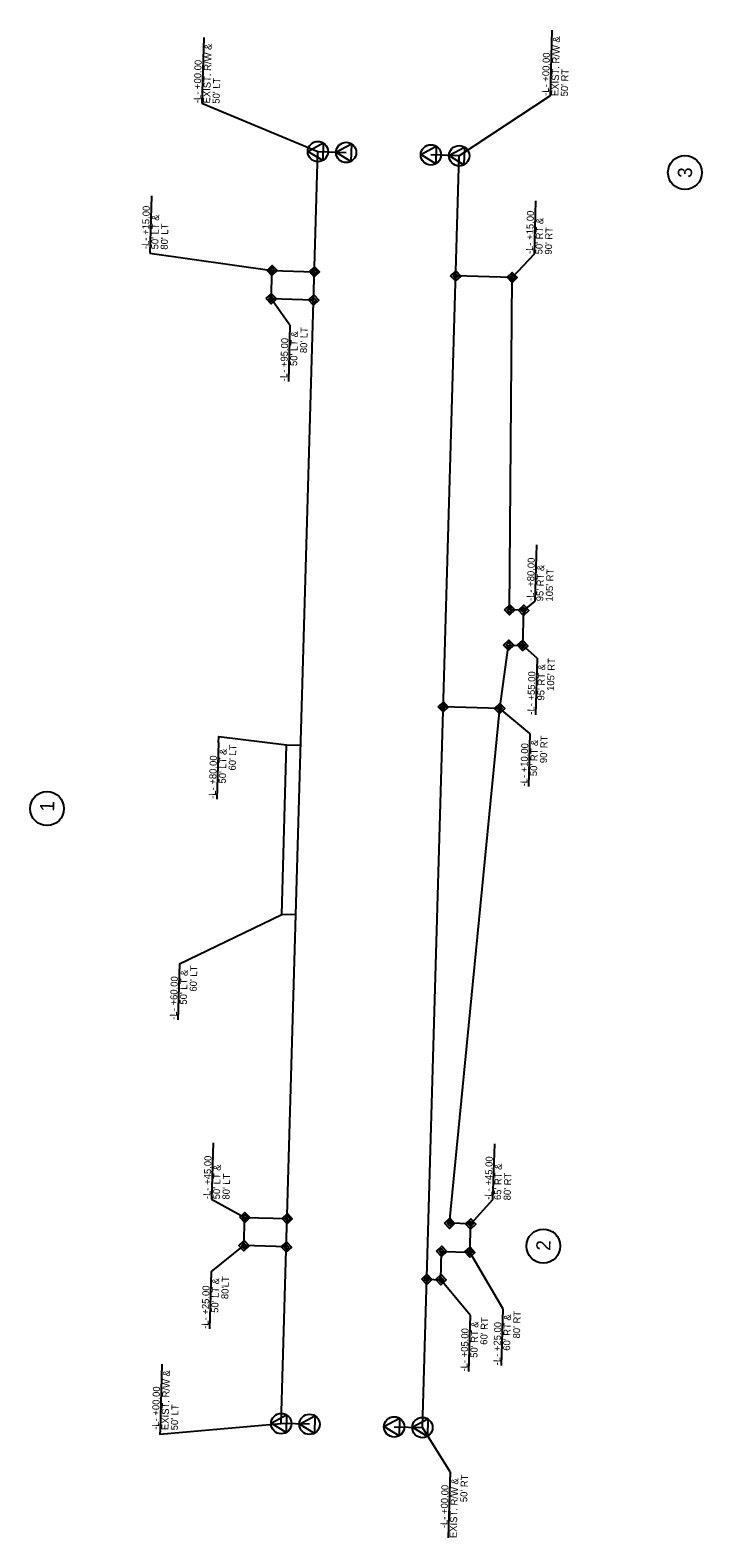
# Model space of a CAD drawing. Extents: x 2097753 to 2098985, y 990579 to 991646.
# Drawn here: x 2098509 to 2098985, y 990579 to 991646 of the extents above; entities that cross this region are included whole.
import ezdxf

# ---------------------------------------------------------------- set-up
doc = ezdxf.new("R2010")
doc.units = 0
for name, color, linetype in [('Prop DSN Text', 7, 'Continuous'), ('Prop Easement Construction', 7, 'Continuous'), ('Prop Easement Construction Station Offsets', 7, 'Continuous'), ('Prop Easement Permanent Drainage Utility', 7, 'Continuous'), ('Prop Easement Permanent Drainage Utility Station Offsets', 7, 'Continuous'), ('Prop Easement Permanent Utility', 7, 'Continuous'), ('Prop Easement Permanent Utility Station Offsets', 7, 'Continuous'), ('Prop Parcel Number CELL', 7, 'Continuous'), ('Prop ROW Marker CELL', 7, 'Continuous'), ('Prop ROW Permanent Easement CELL', 7, 'Continuous'), ('Prop ROW RW Lines', 7, 'Continuous'), ('Prop ROW Station Offsets', 7, 'Continuous')]:
    doc.layers.add(name, color=color, linetype=linetype)

msp = doc.modelspace()

# ---------------------------------------------------------------- linework, layer by layer
at = {"layer": 'Prop Easement Construction'}
msp.add_lwpolyline([(2098697.4, 991019.8), (2098687.5, 991020.1), (2098690.9, 991140), (2098700.9, 991139.7)], dxfattribs=at)
at = {"layer": 'Prop Easement Construction Station Offsets'}
for p, q in [((2098642.7, 991141.6), (2098641.6, 991101.7)), ((2098615.1, 990985.2), (2098614, 990945.5))]:
    msp.add_line(p, q, dxfattribs=at)
for points in [[(2098642.7, 991141.6), (2098642.9, 991145.8), (2098690.9, 991140)], [(2098615.1, 990985.2), (2098687.5, 991020.1)]]:
    msp.add_lwpolyline(points, dxfattribs=at)
at = {"layer": 'Prop Easement Permanent Drainage Utility'}
for p, q in [((2098850.5, 991470.6), (2098810.5, 991471.7)), ((2098848.7, 991235.5), (2098850.5, 991470.6)), ((2098858.7, 991235.2), (2098848.7, 991235.5)), ((2098858, 991210.3), (2098858.7, 991235.2)), ((2098841.7, 991165.7), (2098848, 991210.5)), ((2098848, 991210.5), (2098858, 991210.3))]:
    msp.add_line(p, q, dxfattribs=at)
at = {"layer": 'Prop Easement Permanent Drainage Utility Station Offsets'}
for p, q in [((2098867.1, 991524.8), (2098866, 991487)), ((2098867.7, 991281.5), (2098866.6, 991241.7)), ((2098868.2, 991201.4), (2098867, 991161.3))]:
    msp.add_line(p, q, dxfattribs=at)
for points in [[(2098866, 991487), (2098850.5, 991470.6)], [(2098866.6, 991241.7), (2098858.7, 991235.2)], [(2098868.2, 991201.4), (2098858, 991210.3)]]:
    msp.add_lwpolyline(points, dxfattribs=at)
at = {"layer": 'Prop Easement Permanent Utility'}
for points in [[(2098710, 991454.6), (2098680, 991455.5), (2098680.6, 991475.5), (2098710.6, 991474.6)], [(2098790.1, 990762), (2098800.1, 990761.7), (2098800.6, 990781.7), (2098820.6, 990781.1), (2098821.2, 990801.1), (2098806.2, 990801.6), (2098841.7, 991165.7), (2098801.7, 991166.9)], [(2098690.7, 990784.9), (2098660.7, 990785.8), (2098661.3, 990805.7), (2098691.3, 990804.9)]]:
    msp.add_lwpolyline(points, dxfattribs=at)
at = {"layer": 'Prop Easement Permanent Utility Station Offsets'}
for p, q in [((2098595.2, 991528.3), (2098594, 991487.8)), ((2098693.2, 991436.9), (2098692.1, 991397.1)), ((2098863.1, 991148.1), (2098862, 991110.5)), ((2098638.9, 990858.5), (2098637.7, 990818.7)), ((2098837.9, 990857.9), (2098836.7, 990818.1)), ((2098637.5, 990767.2), (2098636.3, 990726.9)), ((2098844, 990741.3), (2098842.8, 990701)), ((2098820.8, 990736.6), (2098819.7, 990696.7))]:
    msp.add_line(p, q, dxfattribs=at)
for points in [[(2098594, 991487.8), (2098680.6, 991475.5)], [(2098693.2, 991436.9), (2098680, 991455.5)], [(2098863.1, 991148.1), (2098841.7, 991165.7)], [(2098637.7, 990818.7), (2098661.3, 990805.7)], [(2098836.7, 990818.1), (2098821.2, 990801.1)], [(2098637.5, 990767.2), (2098660.7, 990785.8)], [(2098844, 990741.3), (2098820.6, 990781.1)], [(2098820.8, 990736.6), (2098800.1, 990761.7)]]:
    msp.add_lwpolyline(points, dxfattribs=at)
at = {"layer": 'Prop Parcel Number CELL'}
for p, q in [((2098972.8, 991544.8), (2098972.8, 991544.8)), ((2098521.3, 991094.9), (2098521.3, 991094.9)), ((2098872.6, 990785.5), (2098872.6, 990785.5))]:
    msp.add_line(p, q, dxfattribs=at)
for centre in [(2098972.8, 991544.8), (2098521.3, 991094.9), (2098872.6, 990785.5)]:
    msp.add_circle(centre, 12, dxfattribs=at)
at = {"layer": 'Prop ROW Marker CELL'}
for p, q in [((2098713, 991559.6), (2098713, 991559.6)), ((2098733, 991559), (2098733, 991559)), ((2098793, 991557.3), (2098793, 991557.3)), ((2098813, 991556.7), (2098813, 991556.7)), ((2098680.6, 991475.5), (2098680.6, 991475.5)), ((2098710.6, 991474.6), (2098710.6, 991474.6)), ((2098810.5, 991471.7), (2098810.5, 991471.7)), ((2098850.5, 991470.6), (2098850.5, 991470.6)), ((2098680, 991455.5), (2098680, 991455.5)), ((2098710, 991454.6), (2098710, 991454.6)), ((2098848.7, 991235.5), (2098848.7, 991235.5)), ((2098858.7, 991235.2), (2098858.7, 991235.2)), ((2098848, 991210.5), (2098848, 991210.5)), ((2098858, 991210.3), (2098858, 991210.3)), ((2098801.7, 991166.9), (2098801.7, 991166.9)), ((2098841.7, 991165.7), (2098841.7, 991165.7)), ((2098661.3, 990805.7), (2098661.3, 990805.7)), ((2098691.3, 990804.9), (2098691.3, 990804.9)), ((2098806.2, 990801.6), (2098806.2, 990801.6)), ((2098821.2, 990801.1), (2098821.2, 990801.1)), ((2098660.7, 990785.8), (2098660.7, 990785.8)), ((2098690.7, 990784.9), (2098690.7, 990784.9)), ((2098800.6, 990781.7), (2098800.6, 990781.7)), ((2098820.6, 990781.1), (2098820.6, 990781.1)), ((2098790.1, 990762), (2098790.1, 990762)), ((2098800.1, 990761.7), (2098800.1, 990761.7)), ((2098687.1, 990659.9), (2098687.1, 990659.9)), ((2098707.1, 990659.4), (2098707.1, 990659.4)), ((2098767, 990657.6), (2098767, 990657.6)), ((2098787, 990657.1), (2098787, 990657.1))]:
    msp.add_line(p, q, dxfattribs=at)
for points in [[(2098716.4, 991553.2), (2098705.8, 991559.8), (2098716.8, 991565.7)], [(2098736.4, 991552.6), (2098725.8, 991559.2), (2098736.8, 991565.1)], [(2098796.4, 991550.9), (2098785.8, 991557.5), (2098796.7, 991563.4)], [(2098816.4, 991550.3), (2098805.8, 991556.9), (2098816.7, 991562.8)], [(2098690.5, 990653.6), (2098679.9, 990660.2), (2098690.9, 990666.1)], [(2098710.5, 990653), (2098699.9, 990659.6), (2098710.8, 990665.5)], [(2098770.5, 990651.3), (2098759.8, 990657.8), (2098770.8, 990663.8)], [(2098790.5, 990650.7), (2098779.8, 990657.3), (2098790.8, 990663.2)]]:
    msp.add_lwpolyline(points, close=True, dxfattribs=at)
for centre in [(2098713, 991559.6), (2098733, 991559), (2098793, 991557.3), (2098813, 991556.7), (2098687.1, 990659.9), (2098707.1, 990659.4), (2098767, 990657.6), (2098787, 990657.1)]:
    msp.add_circle(centre, 7.2, dxfattribs=at)
at = {"layer": 'Prop ROW Permanent Easement CELL'}
for points in [[(2098677, 991475.6), (2098680.7, 991479.1), (2098684.2, 991475.4), (2098680.5, 991471.9)], [(2098678.8, 991475.5), (2098680.6, 991477.3), (2098682.4, 991475.4), (2098680.5, 991473.7)], [(2098707, 991474.7), (2098710.7, 991478.2), (2098714.1, 991474.5), (2098710.4, 991471)], [(2098708.8, 991474.7), (2098710.6, 991476.4), (2098712.4, 991474.6), (2098710.5, 991472.8)], [(2098806.9, 991471.8), (2098810.6, 991475.3), (2098814.1, 991471.6), (2098810.4, 991468.1)], [(2098808.7, 991471.8), (2098810.6, 991473.5), (2098812.3, 991471.7), (2098810.5, 991469.9)], [(2098846.9, 991470.7), (2098850.6, 991474.2), (2098854.1, 991470.5), (2098850.4, 991467)], [(2098848.7, 991470.6), (2098850.5, 991472.4), (2098852.3, 991470.5), (2098850.4, 991468.8)], [(2098676.4, 991455.6), (2098680.1, 991459.1), (2098683.6, 991455.4), (2098679.9, 991451.9)], [(2098678.2, 991455.5), (2098680, 991457.3), (2098681.8, 991455.4), (2098679.9, 991453.7)], [(2098706.4, 991454.7), (2098710.1, 991458.2), (2098713.6, 991454.5), (2098709.9, 991451)], [(2098708.2, 991454.7), (2098710, 991456.4), (2098711.8, 991454.6), (2098709.9, 991452.8)], [(2098845.1, 991235.6), (2098848.8, 991239.1), (2098852.3, 991235.4), (2098848.6, 991231.9)], [(2098846.9, 991235.6), (2098848.8, 991237.3), (2098850.5, 991235.5), (2098848.7, 991233.7)], [(2098855.1, 991235.3), (2098858.8, 991238.8), (2098862.3, 991235.1), (2098858.6, 991231.6)], [(2098856.9, 991235.3), (2098858.8, 991237), (2098860.5, 991235.2), (2098858.7, 991233.4)], [(2098844.4, 991210.6), (2098848.1, 991214.1), (2098851.6, 991210.4), (2098847.9, 991206.9)], [(2098846.2, 991210.6), (2098848.1, 991212.3), (2098849.8, 991210.5), (2098848, 991208.7)], [(2098854.4, 991210.4), (2098858.1, 991213.8), (2098861.6, 991210.1), (2098857.9, 991206.7)], [(2098856.2, 991210.3), (2098858.1, 991212), (2098859.8, 991210.2), (2098857.9, 991208.5)], [(2098798.1, 991167), (2098801.8, 991170.5), (2098805.3, 991166.7), (2098801.6, 991163.3)], [(2098799.9, 991166.9), (2098801.8, 991168.7), (2098803.5, 991166.8), (2098801.7, 991165.1)], [(2098838.1, 991165.8), (2098841.8, 991169.3), (2098845.3, 991165.6), (2098841.6, 991162.1)], [(2098839.9, 991165.8), (2098841.8, 991167.5), (2098843.5, 991165.6), (2098841.7, 991163.9)], [(2098657.7, 990805.9), (2098661.4, 990809.3), (2098664.9, 990805.6), (2098661.2, 990802.2)], [(2098659.5, 990805.8), (2098661.3, 990807.5), (2098663.1, 990805.7), (2098661.2, 990803.9)], [(2098687.7, 990805), (2098691.4, 990808.5), (2098694.9, 990804.8), (2098691.2, 990801.3)], [(2098689.5, 990804.9), (2098691.3, 990806.7), (2098693.1, 990804.8), (2098691.2, 990803.1)], [(2098802.6, 990801.7), (2098806.3, 990805.2), (2098809.8, 990801.5), (2098806.1, 990798)], [(2098817.6, 990801.2), (2098821.3, 990804.7), (2098824.8, 990801), (2098821.1, 990797.5)], [(2098804.4, 990801.6), (2098806.3, 990803.4), (2098808, 990801.5), (2098806.2, 990799.8)], [(2098819.4, 990801.2), (2098821.3, 990802.9), (2098823, 990801.1), (2098821.1, 990799.3)], [(2098657.1, 990785.9), (2098660.8, 990789.4), (2098664.3, 990785.7), (2098660.6, 990782.2)], [(2098658.9, 990785.8), (2098660.7, 990787.6), (2098662.5, 990785.7), (2098660.6, 990784)], [(2098687.1, 990785), (2098690.8, 990788.5), (2098694.3, 990784.8), (2098690.6, 990781.3)], [(2098688.9, 990784.9), (2098690.7, 990786.7), (2098692.5, 990784.8), (2098690.6, 990783.1)], [(2098797, 990781.8), (2098800.7, 990785.3), (2098804.2, 990781.6), (2098800.5, 990778.1)], [(2098798.8, 990781.8), (2098800.7, 990783.5), (2098802.4, 990781.7), (2098800.6, 990779.9)], [(2098817, 990781.3), (2098820.7, 990784.7), (2098824.2, 990781), (2098820.5, 990777.6)], [(2098818.8, 990781.2), (2098820.7, 990782.9), (2098822.4, 990781.1), (2098820.6, 990779.3)], [(2098786.5, 990762.1), (2098790.2, 990765.6), (2098793.7, 990761.9), (2098790, 990758.4)], [(2098788.3, 990762.1), (2098790.1, 990763.8), (2098791.9, 990762), (2098790, 990760.2)], [(2098796.5, 990761.8), (2098800.2, 990765.3), (2098803.7, 990761.6), (2098800, 990758.1)], [(2098798.3, 990761.8), (2098800.1, 990763.5), (2098801.9, 990761.7), (2098800, 990759.9)]]:
    msp.add_lwpolyline(points, close=True, dxfattribs=at)
at = {"layer": 'Prop ROW RW Lines'}
for points in [[(2098707.1, 990659.4), (2098687.1, 990659.9), (2098713, 991559.6), (2098733, 991559)], [(2098767, 990657.6), (2098787, 990657.1), (2098813, 991556.7), (2098793, 991557.3)]]:
    msp.add_lwpolyline(points, dxfattribs=at)
at = {"layer": 'Prop ROW Station Offsets'}
for p, q in [((2098632.2, 991640.3), (2098630.8, 991593.8)), ((2098878.6, 991645.5), (2098877.3, 991599)), ((2098602.6, 990702), (2098601.3, 990655.5)), ((2098806.7, 990625.7), (2098805.3, 990579.1))]:
    msp.add_line(p, q, dxfattribs=at)
for points in [[(2098630.8, 991593.8), (2098713, 991559.6)], [(2098877.3, 991599), (2098813, 991556.7)], [(2098601.3, 990655.5), (2098601.2, 990652.5), (2098687.1, 990659.9)], [(2098806.7, 990625.7), (2098787, 990657.1)]]:
    msp.add_lwpolyline(points, dxfattribs=at)

# ---------------------------------------------------------------- texts
at = {"layer": 'Prop DSN Text'}
for s, p in [('3', (2098977.7, 991540.9)), ('1', (2098526.3, 991092.7)), ('2', (2098877.5, 990782.1))]:
    msp.add_text(s, height=10, rotation=88.3496, dxfattribs=at).set_placement(p)
at = {"layer": 'Prop Easement Construction Station Offsets'}
for s, p in [("50' LT &", (2098647.8, 991112.6)), ("60' LT", (2098654.8, 991121.8)), ('-L- +80.00', (2098640.7, 991101.8)), ('-L- +60.00', (2098613.1, 990945.6)), ("50' LT &", (2098620.2, 990956.2)), ("60' LT", (2098627.2, 990965.4))]:
    msp.add_text(s, height=5, rotation=88.3496, dxfattribs=at).set_placement(p)
at = {"layer": 'Prop Easement Permanent Drainage Utility Station Offsets'}
for s, p in [('-L- +15.00', (2098865.1, 991487.1)), ("50' RT &", (2098871.9, 991486.9)), ("90' RT", (2098878.6, 991486.7)), ('-L- +80.00', (2098865.7, 991241.7)), ("95' RT &", (2098872.5, 991241.5)), ("105' RT", (2098879.2, 991241.3)), ("105' RT", (2098880.1, 991178.1)), ('-L- +55.00', (2098866.1, 991161.3)), ("95' RT &", (2098873.2, 991171.3))]:
    msp.add_text(s, height=5, rotation=88.3496, dxfattribs=at).set_placement(p)
at = {"layer": 'Prop Easement Permanent Utility'}
for s, p in [('-L- +15.00', (2098593.2, 991490.6)), ("50' LT &", (2098600, 991490.4)), ("80' LT", (2098606.7, 991490.2)), ('-L- +45.00', (2098636.9, 990818.7)), ('-L- +45.00', (2098835.9, 990818.2)), ("50' LT &", (2098643.6, 990818.5)), ("80' LT", (2098650.4, 990818.3)), ("65' RT &", (2098842.6, 990818)), ("80' RT", (2098849.4, 990817.8))]:
    msp.add_text(s, height=5, rotation=88.3496, dxfattribs=at).set_placement(p)
at = {"layer": 'Prop Easement Permanent Utility Station Offsets'}
for s, p in [("80' LT", (2098705.3, 991417)), ('-L- +95.00', (2098691.2, 991397.1)), ("50' LT &", (2098698.3, 991407.9)), ("90' RT", (2098875.1, 991127)), ('-L- +10.00', (2098861.1, 991110.5)), ("50' RT &", (2098868.1, 991117.8)), ("50' LT &", (2098642.5, 990738.2)), (' LT', (2098649.8, 990754.4)), ('-L- +25.00', (2098635.5, 990726.9)), ("80'", (2098649.6, 990747.9)), ("50' RT &", (2098825.9, 990706.4)), ("60' RT", (2098832.9, 990715.6)), ('-L- +25.00', (2098842, 990701.1)), ("60' RT &", (2098849, 990711.4)), ("80' RT", (2098856, 990720.1)), ('-L- +05.00', (2098818.8, 990696.7))]:
    msp.add_text(s, height=5, rotation=88.3496, dxfattribs=at).set_placement(p)
at = {"layer": 'Prop ROW Station Offsets'}
for s, p in [('EXIST. R/W &', (2098883.2, 991598.8)), ('EXIST. R/W &', (2098636.7, 991593.6)), ('-L- +00.00', (2098876.4, 991599)), ('-L- +00.00', (2098629.9, 991593.8)), ("50' RT", (2098889.9, 991598.6)), ("50' LT", (2098643.4, 991593.4)), ('EXIST. R/W &', (2098607.2, 990655.3)), ('-L- +00.00', (2098600.4, 990655.5)), ("50' LT", (2098613.9, 990655.1)), ("50' RT", (2098818.7, 990604.3)), ('-L- +00.00', (2098804.6, 990585.9)), ('EXIST. R/W &', (2098811.2, 990578.9))]:
    msp.add_text(s, height=5, rotation=88.3496, dxfattribs=at).set_placement(p)

doc.saveas('drawing.dxf')
